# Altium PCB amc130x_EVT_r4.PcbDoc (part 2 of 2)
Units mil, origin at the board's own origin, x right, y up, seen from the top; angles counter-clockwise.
Board outline 4400 x 2100 mil, 2 copper layers (Top Layer, Bottom Layer), stack 62 mil thick; 70 components, 42 nets, 166 pads, 13 vias.
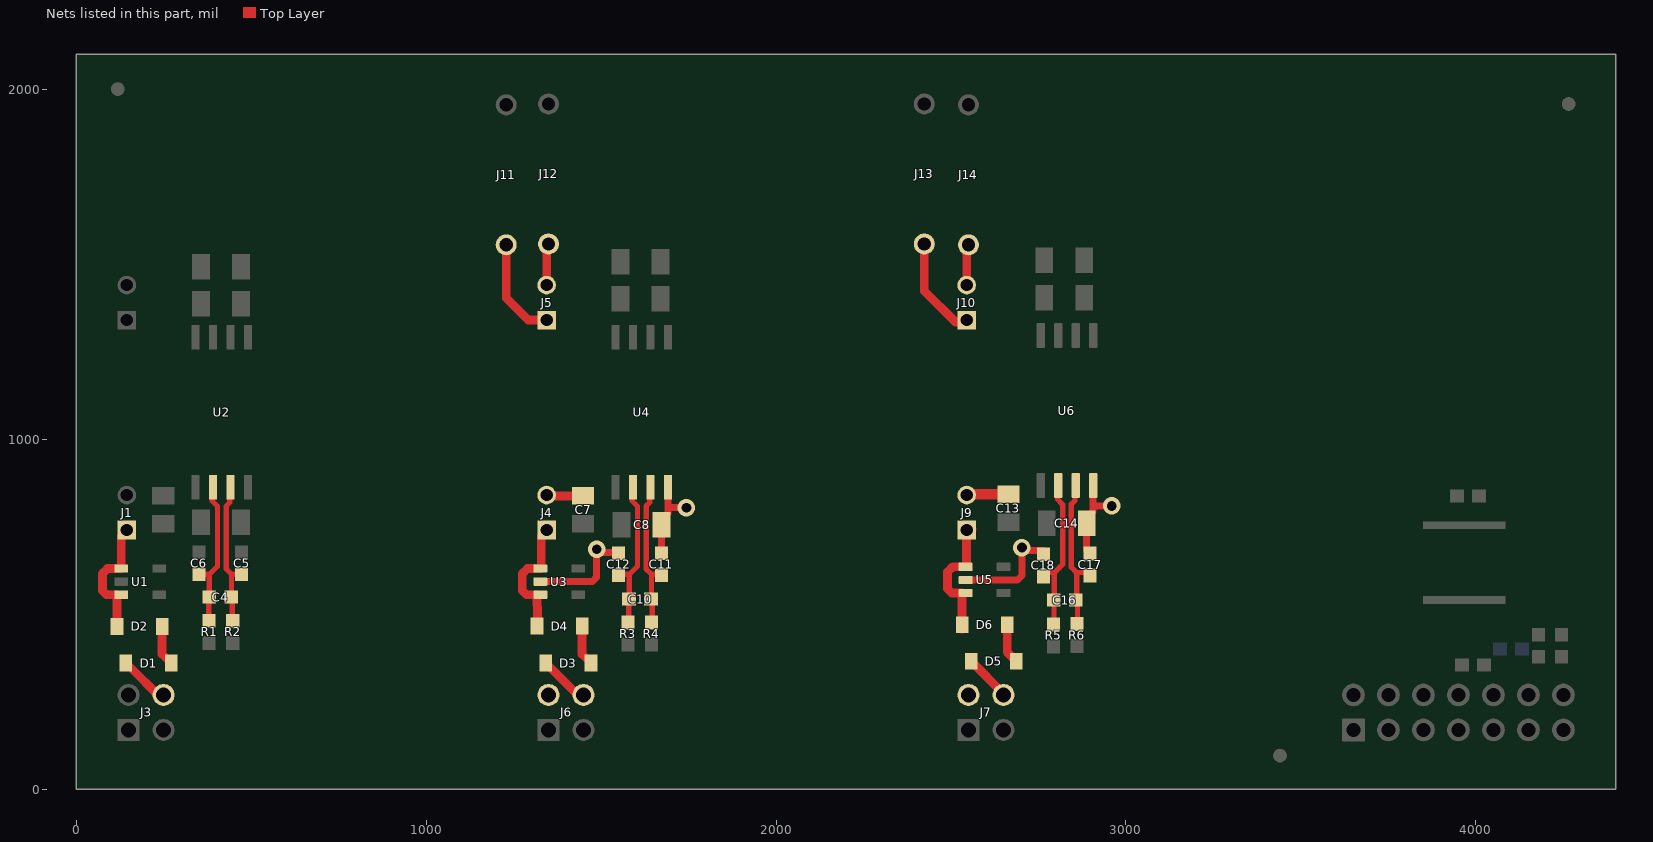
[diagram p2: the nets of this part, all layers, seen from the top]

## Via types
v1: diameter 50, hole 28, Top Layer to Bottom Layer, 13 vias

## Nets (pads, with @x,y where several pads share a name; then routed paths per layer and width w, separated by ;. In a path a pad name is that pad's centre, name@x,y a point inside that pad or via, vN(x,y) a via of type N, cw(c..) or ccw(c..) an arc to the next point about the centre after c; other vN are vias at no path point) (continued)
isoGNDB: C7.1 C8.2 C11.2 C12.2 J4.2 J6.2 U3.2 U4.4 | length 671
  Top Layer w20: U3.2@1329.19,592.6 1475.12,592.6 1487.52,605 v1(1487.52,685) 1488.41,685 1496.93,676.48 C12.2@1550.66,676.48 ; C11.2@1672.85,676.48 C8.2@1672.85,754.71 1665.78,761.78 1691.45,787.45 1691.45,803.72 ; U4.4@1691.45,862 1691.45,803.72 ; v1(1744.21,803.77) 1744.16,803.72 1691.45,803.72
  Top Layer w25: J4.2@1344.63,840 1347.16,837.47 C7.1@1449.02,837.47 C7.1@1446.49,840
isoGNDC: C13.1 C14.2 C17.2 C18.2 J7.2 J9.2 U5.2 U6.4 | length 682
  Top Layer w20: U5.2@2544.19,597.6 2690.12,597.6 2702.52,610 v1(2702.52,690) 2703.41,690 2711.93,681.48 C18.2@2765.66,681.48 ; C17.2@2887.85,681.48 C14.2@2887.85,759.71 2880.78,766.78 2906.45,792.45 2906.45,808.72 ; U6.4@2906.45,867 2906.45,808.72 ; v1(2959.21,808.77) 2959.16,808.72 2906.45,808.72
  Top Layer w30: J9.2@2545,840 2547.47,842.47 C13.1@2664.02,842.47
NetC4_1: C4.1 C6.1 R1.2 U2.2 | length 430.6
  Top Layer w15: C6.1@350.66,613.49 380.33,613.49 ; R1.2@379.01,477.99 379.01,547.02 C4.1@380.33,548.34 380.33,613.49 ; U2.2@389.21,862 389.21,822.86 404.02,808.05 404.02,636.46 381.04,613.49 380.33,613.49
NetC4_2: C4.2 C5.1 R2.2 U2.3 | length 424.8
  Top Layer w15: U2.3@439.21,862 439.21,818.95 430.33,810.08 430.33,810.01 428.96,808.64 428.96,628.59 444.07,613.49 ; R2.2@446.27,477.99 446.27,545.39 C4.2@443.32,548.34 444.07,549.09 444.07,613.49 ; C5.1@472.85,613.49 444.07,613.49
NetC10_1: C10.1 C12.1 R3.2 U4.2 | length 430.6
  Top Layer w15: C12.1@1550.66,613.49 1580.33,613.49 ; R3.2@1579.01,477.99 1579.01,547.02 1580.33,548.34 1580.33,613.49 ; U4.2@1589.21,862 1589.21,822.86 1604.02,808.05 1604.02,636.46 1581.04,613.49 1580.33,613.49
NetC10_2: C10.2 C11.1 R4.2 U4.3 | length 424.8
  Top Layer w15: U4.3@1639.21,862 1639.21,818.95 1630.33,810.08 1630.33,810.01 1628.96,808.64 1628.96,628.59 1644.07,613.49 ; R4.2@1646.27,477.99 1646.27,545.39 1643.32,548.34 1644.07,549.09 1644.07,613.49 ; C11.1@1672.85,613.49 1644.07,613.49
NetC16_1: C16.1 C18.1 R5.2 U6.2 | length 430.6
  Top Layer w15: C18.1@2765.66,618.49 2795.33,618.49 ; R5.2@2794.01,482.99 2794.01,552.02 2795.33,553.34 2795.33,618.49 ; U6.2@2804.21,867 2804.21,827.86 2819.02,813.05 2819.02,641.46 2796.04,618.49 2795.33,618.49
NetC16_2: C16.2 C17.1 R6.2 U6.3 | length 424.8
  Top Layer w15: U6.3@2854.21,867 2854.21,823.95 2845.33,815.08 2845.33,815.01 2843.96,813.64 2843.96,633.59 2859.07,618.49 ; R6.2@2861.27,482.99 2861.27,550.39 2858.32,553.34 2859.07,554.09 2859.07,618.49 ; C17.1@2887.85,618.49 2859.07,618.49
NetD1_1: D1.1 J3.4 | length 152.1
  Top Layer w25: D1.1@142.44,360 J3.4@250,252.44
NetD1_2: D1.2 D2.1 | length 115.2
  Top Layer w25: D2.1@245.69,464.58 245.69,385.69 D1.2@271.38,360
NetD2_2: D2.2 J1.1 U1.1 U1.3 | length 371.7
  Top Layer w25: D2.2@116.76,452.15 D2.2@116.76,464.58 116.76,555.2 87.21,555.2 75.09,567.31 75.09,615.09 90,630 U1.1@129.19,630 129.19,721.39 J1.1@145.09,737.29
NetD3_1: D3.1 J6.4 | length 152.2
  Top Layer w25: D3.1@1342.35,360 1342.44,359.91 J6.4@1450,252.35
NetD3_2: D3.2 D4.1 | length 115.2
  Top Layer w25: D4.1@1445.69,464.58 1445.69,385.69 D3.2@1471.38,360
NetD4_2: D4.2 J4.1 U3.1 U3.3 | length 346
  Top Layer w25: D4.2@1318.7,477.86 1318.7,490.3 1316.76,555.2 1287.21,555.2 1275.09,567.31 1275.09,615.09 1290,630 1329.19,630 1329.19,721.39 J4.1@1345.09,737.29
NetD5_1: D5.1 J7.4 | length 130.9
  Top Layer w25: D5.1@2557.44,365 J7.4@2650,272.44
NetD5_2: D5.2 D6.1 | length 115.2
  Top Layer w25: D6.1@2660.69,469.58 2660.69,390.69 D5.2@2686.38,365
NetD6_2: D6.2 J9.1 U5.1 U5.3 | length 371.9
  Top Layer w25: D6.2@2531.76,456.92 2531.76,560.2 2502.21,560.2 2490.09,572.31 2490.09,620.09 2505,635 2544.19,635 2544.19,726.39 J9.1@2560.09,742.29
NetJ5_1: J5.1 J11.1 | length 293.7
  Top Layer w25: J11.1@1229.02,1555 1229.02,1403.04 1292.06,1340 J5.1@1344.63,1340
NetJ5_2: J5.2 J12.1 | length 123.4
  Top Layer w25: J5.2@1344.63,1440 1344.63,1543.15 J12.1@1358.98,1557.5
NetJ10_1: J10.1 J13.1 | length 294
  Top Layer w25: J13.1@2423.85,1557.5 2423.85,1422.81 2511.94,1334.71 J10.1@2546.66,1334.71
NetJ10_2: J10.2 J14.1 | length 121.1
  Top Layer w25: J10.2@2545,1440 2545,1540.18 J14.1@2559.82,1555
pads on no net: FID1.1 FID2.1 FID3.1 U1.4 U3.4 U5.4

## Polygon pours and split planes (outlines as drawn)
5V_GND on Bottom Layer "BOTTOM_LAYER_5V_GND_P030" (solid, remove dead copper, pour order 30): 50,1271.9 71.9,1250 241,1250 266,1275 266,1575.81 565.19,1875 3785.74,1875 4110.24,1550.5 4110.24,137.45 4197.69,50 4301.85,50 4340,88.15 4340,1945 4235,2050 100,2050 50,2000 50,1571.46
isoGNDC on Bottom Layer "BOTTOM_LAYER_ISOGNDC_P028" (solid, remove dead copper, pour order 28): 2463.15,111.85 2525,50 2950,50 2975,75 2975,866.67 2941.67,900 2536.81,900 2463.15,826.34
isoGNDB on Bottom Layer "BOTTOM_LAYER_ISOGNDB_P026" (solid, remove dead copper, pour order 26): 1268.25,106.75 1325,50 1750,50 1775,75 1775,855 1730,900 1335,900 1268.25,833.25
DGND on Bottom Layer "BOTTOM_LAYER_DGND_P012" (solid, remove dead copper, pour order 12): 4090,96.38 4090,1522.94 3758.47,1854.47 584.39,1854.47 290.38,1560.46 290.8,1276.72 318.95,1248.58 3402.27,1248.58 3500,1150.84 3500,100.94 3550.94,50 4043.61,50
isoGNDA on Bottom Layer "BOTTOM_LAYER_ISOGNDA_P000" (solid, remove dead copper, pour order 0): 71.9,103.1 125,50 550,50 575,75 575,857.33 532.33,900 136.81,900 71.9,835.09
3V3 on Top Layer "TOP_LAYER_3V3_P038" (solid, remove dead copper, pour order 38): 3850,548.34 4084.54,548.34 4090,542.88 4090,96.38 4043.61,50 3923.31,50 3838.32,135 3838.32,540
3V3f on Top Layer "TOP_LAYER_3V3F_P036" (solid, remove dead copper, pour order 36): 4090,757.99 4090,1522.94 3758.47,1854.47 584.39,1854.47 290.69,1560.77 290.69,1248.58 3397.82,1248.58 3500,1146.39 3500,325.92 3625,224.46 3775,225 3800,250 3800,700 3825.05,725.05 4060.56,728.55
5V on Top Layer "TOP_LAYER_5V_P034" (solid, remove dead copper, pour order 34): 50,1271.9 71.9,1250 241,1250 266,1275 266,1575.81 565.19,1875 3783.84,1875 4110.24,1548.6 4110.24,137.45 4197.69,50 4301.85,50 4340,88.15 4340,1945 4235,2050 105,2050 50,1995 50,1571.46

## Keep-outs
Keep-Out Layer:
  text ".Layer_Name" at 577,-858.49 h60

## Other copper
Top Layer:
  text ".Layer_Name" at 577,-858.49 h60
Bottom Layer:
  text ".Layer_Name" at 577,-858.49 h60

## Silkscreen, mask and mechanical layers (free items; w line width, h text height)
Top Overlay:
  lines w25: 25,1075 211.8,1075 ; 554.65,1075 1414.98,1075 ; 1775,1075 2629.07,1075 ; 2976.86,1075 3250,1074.84 3250,50
  text "Inverter Current Sensing" at 241,1875 h80
  text "'.PRJ_Number'.PCB_Rev" at 244.02,1780 h70
  text "LOW VOLTAGE" at 780,1105 h60
  text "LOW VOLTAGE" at 2060,1105 h60
  text "HIGH VOLTAGE" at 775,1005 h60
  text "HIGH VOLTAGE" at 2055,1005 h60
  text "Danger" at 1930,744.51 h100
  text "High Voltage" at 1830,636.06 h100
  text "LOW VOLTAGE" at 3315,428.15 h60 r90
  text "HIGH VOLTAGE" at 3220,422.64 h60 r90
  text ".Layer_Name" at 577,-858.49 h60
Bottom Overlay:
  lines w25: 55,1075 1414.98,1075 3250,1074.84 3250,50
  text "LOW VOLTAGE" at 780,1105 h60
  text "LOW VOLTAGE" at 2760,1105 h60
  text "HIGH VOLTAGE" at 775,1005 h60
  text "HIGH VOLTAGE" at 2755,1005 h60
  text "Danger" at 2212.85,752.35 h100
  text "High Voltage" at 2370,643.41 h100
  text "LOW VOLTAGE" at 3315,628.15 h60 r90
  text "HIGH VOLTAGE" at 3220,622.64 h60 r90
  text ".Layer_Name" at 577,-858.49 h60
Top Paste:
  text ".Layer_Name" at 577,-858.49 h60
Bottom Paste:
  text ".Layer_Name" at 577,-858.49 h60
Top Solder:
  text ".Layer_Name" at 577,-858.49 h60
  text ".Layer_Name" at 577,-858.49 h60
Bottom Solder:
  text ".Layer_Name" at 577,-858.49 h60
Drill Guide:
  text ".Layer_Name" at 577,-858.49 h60
M1 Board Outline:
  the board outline again, w10
  text ".Layer_Name" at 577,-858.49 h60
M2 Board Dimensions:
  rectangle: 0,-275 125,-150
  rectangle: 125,-400 500,-275
  lines w7: 0,-275 1000,-275 ; 125,-400 125,-150 ; 250,-400 250,-150 ; 500,-400 500,-150 ; 750,-400 750,-150 ; 0,-400 1000,-400 1000,-150 0,-150 0,-400
  text ".Layer_Name" at 577,-858.49 h60
M3 3D STEP Top:
  text ".Layer_Name" at 577,-858.49 h60
M4 3D STEP Bottom:
  text ".Layer_Name" at 577,-858.49 h60
M5 Assembly Top:
  lines w10: -292,-930.17 6308,-930.17 ; -292,-726.83 6310,-726.83 ; -292,-523.5 -292,-1133.5 3713,-1133.5 6310,-1133.5 6310,-523.5 -291.5,-523.5 -291.5,-1133.5 1284,-1133.5 ; 2173,-1133.5 2173,-523.5 ; 3440,-726.83 3440,-523.5 ; 4280,-726.83 4280,-523.5 ; 4902,-1140 4902,-937.17
  text "COMPONENTS MARKED 'DNP' SHOULD NOT BE POPULATED." at 1153.5,-318.5 h60
  text "ASSEMBLY VARIANT:" at 1153,-434 h60
  text ".VariantName" at 2189,-434 h60
  text "PCB VIEWED FROM TOP SIDE" at -228.5,-655.67 h60
  text "BOARD #:" at 2248,-655.67 h60
  text ".PRJ_Number" at 2793.5,-655.67 h60
  text "REV:" at 3638,-655.67 h60
  text ".PCB_Rev" at 3929.5,-655.67 h60
  text "SVN REV:" at 4476,-655.67 h60
  text ".VersionControl_RevNumber" at 4982,-655.67 h60
  text "TID #:" at 2248,-859 h60
  text ".TID" at 2793.5,-859 h60
  text "PLOT NAME =" at -228.5,-1064.34 h60
  text ".plot_File_Name" at 577,-1064.34 h60
  text "GENERATED    :" at 2250,-1064.34 h60
  text ".Print_Date" at 3119.5,-1064.34 h60
  text ".Print_Time" at 3848.5,-1064.34 h60
  text "TEXAS INSTRUMENTS" at 5113,-1064.34 h60
M6 Assembly Bottom:
  lines w10: -292.5,-727.33 6309.5,-727.33 ; -290.5,-930.67 6309.5,-930.67 ; 1115.5,-1140.5 1115.5,-937.67 ; 1737.5,-727.33 1737.5,-524 ; 2577.5,-727.33 2577.5,-524 ; 3844.5,-1134 3844.5,-524 ; 4733.5,-1134 6309,-1134 6309,-524 -292.5,-524 -292.5,-1134 2304.5,-1134 6309.5,-1134 6309.5,-524
  text "COMPONENTS MARKED 'DNP' SHOULD NOT BE POPULATED." at 6102,-318 h60
  text ".VariantName" at 5058,-434 h60
  text "ASSEMBLY VARIANT:" at 6097,-434 h60
  text ".VersionControl_RevNumber" at 1035.5,-656.17 h60
  text "SVN REV:" at 1541.5,-656.17 h60
  text ".PCB_Rev" at 2088,-656.17 h60
  text "REV:" at 2379.5,-656.17 h60
  text ".PRJ_Number" at 3224,-656.17 h60
  text "BOARD #:" at 3769.5,-656.17 h60
  text "PCB VIEWED FROM BOTTOM SIDE" at 6246,-656.17 h60
  text ".TID" at 3224,-859.5 h60
  text "TID #:" at 3769.5,-859.5 h60
  text "TEXAS INSTRUMENTS" at 904.5,-1064.84 h60
  text ".Print_Time" at 2169,-1064.84 h60
  text ".Print_Date" at 2898,-1064.84 h60
  text "GENERATED    :" at 3767.5,-1064.84 h60
  text ".plot_File_Name" at 5440.5,-1064.84 h60
  text "PLOT NAME =" at 6246,-1064.84 h60
M9 Title Sheet:
  drawing of 57 lines, arcs and shapes, not listed
  text "1" at 739.84,8036.5 h70
  text "2" at 3235.5,8036.5 h70
  text "3" at 5724.84,8036.5 h70
  text "4" at 8231.51,8036.5 h70
  text "5" at 10730.5,8036.5 h70
  text "6" at 13235.5,8036.5 h70
  text "A" at -416.5,6893.5 h70
  text "A" at 14383.5,6893.5 h70
  text "B" at -416.5,4513.5 h70
  text "B" at 14383.5,4513.5 h70
  text "C" at -416.5,2138.5 h70
  text "C" at 14383.5,2138.5 h70
  text "PROJECT TITLE:" at 11343.5,277.5 h45
  text ".PRJ_Title" at 11393.5,144.17 h70
  text "DESIGNED FOR:" at 11343.5,-23.5 h45
  text ".PRJ_Customer" at 11393.5,-163.5 h70
  text "D" at -416.5,-231.5 h70
  text "D" at 14383.5,-231.5 h70
  text "FILE NAME:" at 11343.5,-323.5 h45
  text ".PCB_File_Name_No_Path" at 11393.5,-443.5 h70
  text "Texas Instruments (TI) and/or its licensors do not warrant the accuracy or completeness of this specification" at 6374,-605.34 h45
  text "ENGINEER:" at 11343.5,-613.5 h45
  text "LAYOUT BY:" at 12848.5,-613.5 h45
  text "or any information contained therein. TI and/or its licensors do not warrant that this design will meet" at 6329.01,-718 h45
  text ".PRJ_Engineer" at 11393.5,-768.49 h70
  text ".PCB_Layout" at 12899,-768.49 h70
  text "the specifications, will be suitable for your application or fit for any particular purpose, or will operate in" at 6329.01,-830.67 h45
  text ".Layer_Name" at 577,-858.49 h60
  text "ALTIUM DESIGNER VERSION:" at 12848.5,-923.5 h45
  text "an implementation. TI and/or its licensors do not warrant that the design is production worthy. You should" at 6329.01,-943.33 h45
  text "completely validate and test your design implementation to confirm the system functionality for your application." at 6374,-1056 h45
  text ".print_Scale" at 11393.5,-1056.83 h70
  text ".Application_BuildNumber" at 12899,-1056.83 h70
  text "1" at 739.84,-1263.5 h70
  text "2" at 3235.5,-1263.5 h70
  text "3" at 5724.84,-1263.5 h70
  text "4" at 8231.51,-1263.5 h70
  text "5" at 10730.5,-1263.5 h70
  text "6" at 13235.5,-1263.5 h70
M10 Fab Notes:
  drawing of 189 lines, arcs and shapes, not listed
  text "DESIGN INFORMATION" at 12382.02,6356.17 h60
  text "MIN. TRACK WIDTH:" at 11737.46,6224.05 h60
  text "8" at 12833.7,6224.05 h60
  text "MIL" at 12988.46,6224.05 h60
  text "MIN. CLEARANCE:" at 11737.46,6099.92 h60
  text "0.2" at 12773.7,6099.93 h60
  text "mm" at 12988.46,6099.92 h60
  text "MIN. VIA PAD SIZE:" at 11737.46,5975.8 h60
  text "24" at 12803.71,5975.8 h60
  text "MIL" at 12988.46,5975.8 h60
  text "0.05mm (2MIL)" at 12432.46,5845.9 h60
  text "MINIMUM ANNULAR RING" at 11408.23,5837.67 h60
  text "EXTERNAL" at 13140.46,5837.67 h60
  text "PER" at 11608.23,5727.55 h60
  text "IPC-D-275 CLASS 2 LEVEL C" at 11828.23,5727.54 h60
  text "MIL, HOLES" at 13316.46,5627.07 h60
  text "+/-" at 12924,5618.48 h60
  text "+/-" at 13778,5618.48 h60
  text "REGISTRATION TOLERANCES:" at 11408.23,5617.42 h60
  text "METAL" at 12608,5617.42 h60
  text "5" at 13184.2,5617.42 h60
  text "3" at 14017.2,5617.42 h60
  text "MIL" at 14133.46,5617.42 h60
  text "HOLE SIZE TOLERANCE (UNLESS OTHERWISE SPECIFIED):" at 11408.23,5519.1 h60
  text "+/-" at 13778,5516.23 h60
  text "3" at 14017.2,5515.17 h60
  text "MIL" at 14133.46,5515.17 h60
  text "MATERIAL:" at 11333.46,5377.52 h60
  text "FR-4 High Tg" at 12319.9,5249 h60
  text "X" at 12175.46,5241.01 h60
  text "FR-408" at 11754.46,5236.49 h60
  text "OTHER" at 13242.46,5236.49 h60
  text "62 MIL (1.6mm) +/-10%" at 12074.56,5093.46 h60
  text "X" at 11954.46,5091.01 h60
  text "THICKNESS:" at 11408.23,5085.24 h60
  text "OTHER" at 13359.46,5085.24 h60
  text "TOLERANCE:" at 11408.23,4946.92 h60
  text "X" at 12256.46,4946.92 h60
  text "ANSI IPC-6012 TYPE 3 CLASS 2" at 12434.48,4946.92 h60
  text "OTHER +/-" at 12434.46,4802.73 h60
  text "BOW & TWIST:" at 11408.23,4657.54 h60
  text "X" at 12256.46,4657.54 h60
  text "ANSI IPC-6012 TYPE 3 CLASS 2" at 12434.48,4657.54 h60
  text "OTHER +/-" at 12434.46,4510.85 h60
  text "DRILLING:" at 11333.46,4380.23 h60
  text "NC_DRILL FILES" at 13094.46,4275.04 h60
  text "REFERENCE:" at 11408.23,4271.1 h60
  text "X" at 12065.46,4271.01 h60
  text "AS SHOWN" at 12243.46,4271.1 h60
  text "X" at 12966.46,4271.1 h60
  text "OTHER" at 13392.46,4128.85 h60
  text "PTH COPPER THICKNESS:" at 11407.91,4125.32 h60
  text "X" at 12547.14,4125.32 h60
  text "20-30 um" at 12675.14,4125.32 h60
  text "BOARD FINISH:" at 11333.46,3977.73 h60
  text "SILKSCREEN:" at 11488.68,3867.6 h60
  text "X" at 12446.46,3867.6 h60
  text "TOP" at 12563.46,3867.6 h60
  text "X" at 12956.46,3867.6 h60
  text "BOTTOM" at 13074.46,3867.6 h60
  text "SILKSCREEN COLOR:" at 11488.68,3712.41 h60
  text "X" at 12445.46,3712.41 h60
  text "WHITE" at 12563.46,3712.41 h60
  text "OTHER" at 13074.46,3712.41 h60
  text "X" at 12576.46,3568.96 h60
  text "GREEN" at 12694.46,3568.96 h60
  text "OTHER" at 13312.46,3568.96 h60
  text "SOLDER RESIST COLOR:" at 11488.68,3562.1 h60
  text "X" at 12576.46,3414.71 h60
  text "MATTE" at 12694.46,3414.71 h60
  text "SEMI-GLOSS" at 13312,3414.07 h60
  text "IMMERSION GOLD (ENIG)" at 12394.46,3241.94 h60
  text "ENEPIG" at 13732,3234.72 h60
  text "SURFACE FINISH:" at 11333.46,3233.72 h60
  text "X" at 12216.46,3233.72 h60
  text "IMM. TIN/SILVER OR EQUIV" at 11663,3096.4 h60
  text "OTHER" at 13094.46,3092.47 h60
  text "ARRAY/PANEL:" at 11333.46,2937.09 h60
  text "CUT AND TRIM PER M1 BOARD OUTLINE" at 12394.46,2928.87 h60
  text "N.C. ROUTE" at 12394.46,2792.9 h60
  text "X" at 13082.46,2792.9 h60
  text "V. SCORE" at 13260.46,2792.9 h60
  text "CERTIFICATION:" at 11333.46,2663.77 h60
  text "MATERIALS AND WORKMANSHIP FOR ALL PCBS" at 12058.46,2663.77 h60
  text "TO MEET OR EXCEED THE REQUIREMENTS OF:" at 12058.46,2569.71 h60
  text "X" at 11695.97,2441.08 h60
  text "ANSI IPC-A-600F CLASS ->" at 11823.96,2441.08 h60
  text "X" at 13471.97,2441.08 h60
  text "2" at 13581.96,2441.08 h60
  text "1" at 13266.96,2439.58 h60
  text "3" at 13935.96,2439.58 h60
  text "X" at 12507.97,2293.39 h60
  text "RoHS" at 12635.96,2293.39 h60
  text "OTHER" at 13280.36,2293.39 h60
  text "PER ORDER" at 13677.42,2293.39 h60
  text "ALL BOARDS MUST MEET OR EXCEED UL94-V0 REQUIREMENTS." at 11361,2139.57 h60
  text "PCB MUST BEAR THE UL94V-0 UL REGISTERED MATERIAL ID NUMBER" at 11361,2023.5 h60
  text "ADDITIONAL REQUIREMENTS:" at 11333.46,1854.08 h60
  text "MICROSECTION:" at 11408.23,1746.95 h60
  text "YES" at 12313.96,1746.95 h60
  text "REQUIRED" at 13175.46,1602.62 h60
  text "BARE BOARD ELEC. TEST:" at 11408.23,1599.76 h60
  text "NONE" at 12713.96,1599.76 h60
  text "X" at 13057.46,1599.76 h60
  text "PER ORDER" at 13767.46,1599.76 h60
  text "XX MIL VIAS REQUIRE NON-CONDUCTIVE FILL AND PLANARIZE" at 11576.38,1394.82 h59
  text "XX MIL VIAS REQUIRE CONDUCTIVE FILL AND PLANARIZE" at 11584.38,1290.84 h60
  text "OUTER XX MIL TRACES REQUIRE 50 OHM SINGLE-ENDED IMPEDANCE" at 11583.39,1127.46 h58
  text "LAYER 2 & 3 (INNER LAYERS) XX MIL WIDE, XX MIL SPACE / TRACES REQUIRE 100 OHM DIFFERENTIAL IMPEDANCE" at 11575.39,891.74 h60
  text ".Layer_Name" at 577,-858.49 h60
M11 Gerber Information:
  lines w10: -292,-930.17 6308,-930.17 ; -292,-726.83 6310,-726.83 ; -292,-523.5 -292,-1133.5 3713,-1133.5 6310,-1133.5 6310,-523.5 -291.5,-523.5 -291.5,-1133.5 1284,-1133.5 ; 2173,-1133.5 2173,-523.5 ; 3440,-726.83 3440,-523.5 ; 4280,-726.83 4280,-523.5 ; 4902,-1140 4902,-937.17
  text "ALL ARTWORK VIEWED FROM TOP SIDE" at -228.5,-655.67 h60
  text "BOARD #:" at 2248,-655.67 h60
  text ".PRJ_Number" at 2793.5,-655.67 h60
  text "REV:" at 3638,-655.67 h60
  text ".PCB_Rev" at 3929.5,-655.67 h60
  text "SVN REV:" at 4476,-655.67 h60
  text ".VersionControl_RevNumber" at 4982,-655.67 h60
  text "LAYER NAME =" at -228.5,-858.49 h60
  text "TID #:" at 2248,-859 h60
  text ".TID" at 2793.5,-859 h60
  text "PLOT NAME =" at -228.5,-1064.34 h60
  text ".plot_File_Name" at 577,-1064.34 h60
  text "GENERATED    :" at 2250,-1064.34 h60
  text ".Print_Date" at 3119.5,-1064.34 h60
  text ".Print_Time" at 3848.5,-1064.34 h60
  text "TEXAS INSTRUMENTS" at 5113,-1064.34 h60
M12 Stackup:
  drawing of 191 lines, arcs and shapes, not listed
  text "Layer" at 9811.59,7109.94 h60
  text "Name" at 10221.51,7109.94 h60
  text "Material" at 11151.25,7109.94 h60
  text "Thickness" at 12011.02,7109.94 h60
  text "Constant" at 12660.85,7109.94 h60
  text "Board Layer Stack" at 13230.71,7109.94 h60
  text "1" at 9811.59,6989.94 h60
  text "Top Overlay" at 10221.51,6989.94 h60
  text "2" at 9811.59,6869.94 h60
  text "Top Solder" at 10221.51,6869.94 h60
  text "Solder Resist" at 11151.25,6869.94 h60
  text "0.40mil" at 12011.02,6869.94 h60
  text "3.5" at 12660.85,6869.94 h60
  text "3" at 9811.59,6749.94 h60
  text "Top Layer" at 10221.51,6749.94 h60
  text "Copper" at 11151.25,6749.94 h60
  text "1.40mil" at 12011.02,6749.94 h60
  text "4" at 9811.59,6629.94 h60
  text "Dielectric1" at 10221.51,6629.94 h60
  text "FR-4" at 11151.25,6629.94 h60
  text "59.20mil" at 12011.02,6629.94 h60
  text "4.8" at 12660.85,6629.94 h60
  text "5" at 9811.59,6509.94 h60
  text "Bottom Layer" at 10221.51,6509.94 h60
  text "Copper" at 11151.25,6509.94 h60
  text "1.40mil" at 12011.02,6509.94 h60
  text "6" at 9811.59,6389.94 h60
  text "Bottom Solder" at 10221.51,6389.94 h60
  text "Solder Resist" at 11151.25,6389.94 h60
  text "0.40mil" at 12011.02,6389.94 h60
  text "3.5" at 12660.85,6389.94 h60
  text "7" at 9811.59,6269.94 h60
  text "Bottom Overlay" at 10221.51,6269.94 h60
  text ".Layer_Name" at 577,-858.49 h60
M13 Component Bodies Top:
  text ".Layer_Name" at 577,-858.49 h60
M14 Component Bodies Bottom:
  text ".Layer_Name" at 577,-858.49 h60
M15 Courtyards Top:
  text ".Layer_Name" at 577,-858.49 h60
M16 Courtyards Bottom:
  text ".Layer_Name" at 577,-858.49 h60
Drill Drawing:
  circle w10: c6049.85,1578.59 r27.63
  lines w10: 6022.23,1081.31 6049.85,1053.68 6077.48,1081.31 6049.85,1108.93 6022.23,1081.31 ; 6022.23,1178 6022.23,1191.81 6036.04,1205.63 6022.23,1219.44 6022.23,1233.25 6036.04,1233.25 6049.85,1219.44 6063.67,1233.25 6077.48,1233.25 6077.48,1219.44 6063.67,1205.63 6077.48,1191.81 6077.48,1178 6063.67,1178 6049.85,1191.81 6036.04,1178 6022.23,1178 ; 6022.23,1302.32 6077.48,1302.32 6077.48,1357.57 6022.23,1357.57 6022.23,1302.32 ; 6022.23,1440.45 6036.04,1440.45 6036.04,1426.64 6063.67,1426.64 6063.67,1440.45 6077.48,1440.45 6077.48,1468.08 6063.67,1468.08 6063.67,1481.89 6036.04,1481.89 6036.04,1468.08 6022.23,1468.08 6022.23,1440.45
  lines w12: 5972.14,1016.38 9203.63,1016.38 ; 5972.14,1637.98 9203.63,1637.98 ; 6310,892.06 6310,1762.3 ; 6642,892.06 6642,1762.3 ; 7278.56,892.06 7278.56,1762.3 ; 7537.7,892.06 7537.7,1762.3 ; 7912.86,892.06 7912.86,1762.3 ; 8637.19,892.06 8637.19,1762.3 ; 5972.14,892.06 9203.63,892.06 9203.63,1762.3 5972.14,1762.3 5972.14,892.06
  text "Symbol" at 6046.73,1675.28 h72
  text "Quantity" at 6347.3,1675.28 h72
  text "Finished Hole Size" at 6679.3,1675.28 h72
  text "Plated" at 7315.86,1675.28 h72
  text "Hole Type" at 7575,1675.28 h72
  text "Drill Layer Pair" at 7950.16,1675.28 h72
  text "Hole Tolerance" at 8674.49,1675.28 h72
  text "13" at 6347.3,1550.96 h60
  text "28.00mil (0.711mm)" at 6679.3,1550.96 h60
  text "PTH" at 7315.86,1550.96 h60
  text "Round" at 7575,1550.96 h60
  text "Top Layer - Bottom Layer" at 7950.16,1550.96 h60
  text "12" at 6347.3,1426.64 h60
  text "35.04mil (0.890mm)" at 6679.3,1426.64 h60
  text "PTH" at 7315.86,1426.64 h60
  text "Round" at 7575,1426.64 h60
  text "Top Layer - Bottom Layer" at 7950.16,1426.64 h60
  text "8" at 6347.3,1302.32 h60
  text "38.00mil (0.965mm)" at 6679.3,1302.32 h60
  text "PTH" at 7315.86,1302.32 h60
  text "Round" at 7575,1302.32 h60
  text "Top Layer - Bottom Layer" at 7950.16,1302.32 h60
  text "14" at 6347.3,1178 h60
  text "39.37mil (1.000mm)" at 6679.3,1178 h60
  text "PTH" at 7315.86,1178 h60
  text "Round" at 7575,1178 h60
  text "Top Layer - Bottom Layer" at 7950.16,1178 h60
  text "12" at 6347.3,1053.68 h60
  text "43.31mil (1.100mm)" at 6679.3,1053.68 h60
  text "PTH" at 7315.86,1053.68 h60
  text "Round" at 7575,1053.68 h60
  text "Top Layer - Bottom Layer" at 7950.16,1053.68 h60
  text "59 Total" at 6347.3,929.36 h60
  text ".Layer_Name" at 577,-858.49 h60
M17 Embedded Cavity:
  text ".Layer_Name" at 577,-858.49 h60
M18 Embedded Assembly:
  text ".Layer_Name" at 577,-858.49 h60
M19 Embedded Keepout:
  text ".Layer_Name" at 577,-858.49 h60

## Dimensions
0,0 to 0,2100 on M2 Board Dimensions
0,0 to 4400,0 on M2 Board Dimensions
0,-400 to 1000,-400 on M2 Board Dimensions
